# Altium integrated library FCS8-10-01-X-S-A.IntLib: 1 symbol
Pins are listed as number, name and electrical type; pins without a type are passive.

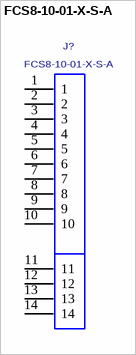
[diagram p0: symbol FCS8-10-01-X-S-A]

## FCS8-10-01-X-S-A
designator J?
FCS8 Socket Assembly, 20-Pins, w/ Alignment Pins; MANUFACTURER: SAMTEC
footprint FCS8-10-01-X-S-A
pins: 1, 2, 3, 4, 5, 6, 7, 8, 9, 10, 11, 12, 13, 14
